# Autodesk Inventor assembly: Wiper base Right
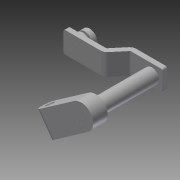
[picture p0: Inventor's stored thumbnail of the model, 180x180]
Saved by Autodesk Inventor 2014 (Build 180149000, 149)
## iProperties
Created: 2006-03
Part Number: Wiper base Right
Document SubType Name: Assembly
Designer: Autodesk, Inc.
Mass: 335.369 g
Surface Area: 167.286 cm^2
Volume: 43.2734 cm^3
Density: 7.75 g/cm^3
Author: Autodesk, Inc.
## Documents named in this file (5)
- C:\Users\iTools\Desktop\tutorial files\Dynamic Simulation 4\Components\Wiper base Right.iam
- C:\Users\iTools\Desktop\tutorial files\Dynamic Simulation 4\Components\Axis_Right.ipt
- C:\Users\iTools\Desktop\tutorial files\Dynamic Simulation 4\Components\Support_Wiper.ipt
- C:\Users\iTools\Desktop\tutorial files\Dynamic Simulation 4\Components\Crank_right.ipt
- C:\Users\iTools\Desktop\tutorial files\Dynamic Simulation 4\Components\Pawn.ipt
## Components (4 placed, 4 different names)
1. Axis_Right:1 — Mate:18, Flush:4, Angle:9, Mate:32, Mate:33, Mate:34
2. Support_Wiper:1 — Mate:18, Flush:4, Angle:9
3. Crank_right:1 — Mate:29, Mate:30, Mate:31, Mate:32, Mate:33, Mate:34, Mate:35, Mate:36, Angle:10, Angle:11
4. Pawn:1 — Mate:35, Mate:36, Mate:39, Flush:5
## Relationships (15: Mate 10, Angle 3, Flush 2)
- Mate:18: Axis_Right:1 ↔ Support_Wiper:1
- Flush:4: Axis_Right:1 ↔ Support_Wiper:1
- Angle:9: Axis_Right:1 ↔ Support_Wiper:1
- Mate:29: Crank_right:1
- Mate:30: Crank_right:1
- Mate:31: Crank_right:1
- Mate:32: Axis_Right:1 ↔ Crank_right:1
- Mate:33: Axis_Right:1 ↔ Crank_right:1
- Mate:34: Axis_Right:1 ↔ Crank_right:1
- Mate:35: Crank_right:1 ↔ Pawn:1
- Mate:36: Crank_right:1 ↔ Pawn:1
- Mate:39: Pawn:1
- Angle:10: Crank_right:1
- Flush:5: Pawn:1
- Angle:11: Crank_right:1
